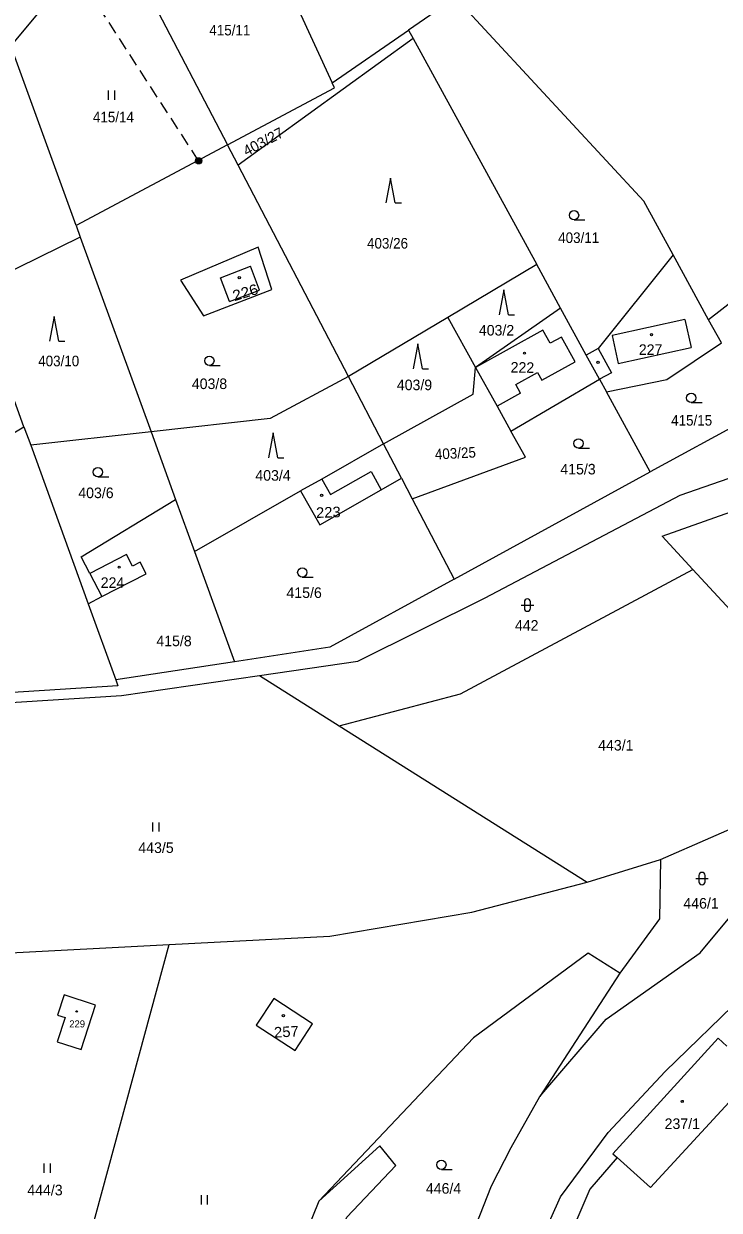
# Model space of a CAD drawing. Extents: x -754445 to -751443, y -1030748 to -1028224.
# Drawn here: x -753502.6 to -753390.6, y -1029073.5 to -1028882.4 of the extents above; entities that cross this region are included whole.
import ezdxf
from ezdxf.enums import TextEntityAlignment as Align

# ---------------------------------------------------------------- set-up
doc = ezdxf.new("R2010")
doc.units = 0
doc.header["$LTSCALE"] = 0.68
doc.linetypes.add('MEDIUM_DASHED', pattern=[4.5, 3, -1.5])
for name, color, linetype, lineweight in [('1', 7, 'Continuous', 25), ('3', 7, 'Continuous', 25), ('4', 7, 'Continuous', 13), ('5', 7, 'Continuous', 25), ('6', 7, 'Continuous', 25)]:
    doc.layers.add(name, color=color, linetype=linetype, lineweight=lineweight)
doc.layers.add('2', color=7, linetype='Continuous')

msp = doc.modelspace()

# ---------------------------------------------------------------- linework, layer by layer
at = {"layer": '1'}
for p, q in [((-753486.58, -1028869.72), (-753469.8, -1028901.88)), ((-753494.17, -1028914.88), (-753504.67, -1028885.95)), ((-753439.88, -1028884.76), (-753468.09, -1028905.15)), ((-753493.5, -1028916.72), (-753510.61, -1028925.11)), ((-753392.33, -1028930.04), (-753398.05, -1028919.59)), ((-753434.31, -1028929.68), (-753450.34, -1028939.19)), ((-753390.28, -1028933.79), (-753392.33, -1028930.04)), ((-753444.68, -1028950.03), (-753450.34, -1028939.19)), ((-753424.16, -1028947.97), (-753409.88, -1028939.64)), ((-753409.88, -1028939.64), (-753408.77, -1028941.67)), ((-753401.72, -1028954.55), (-753408.77, -1028941.67)), ((-753384.17, -1028944.96), (-753401.72, -1028954.55)), ((-753502.57, -1028947.27), (-753501.49, -1028950.26)), ((-753433.31, -1028971.82), (-753401.72, -1028954.55)), ((-753441.79, -1028955.57), (-753440.07, -1028958.87)), ((-753440.07, -1028958.87), (-753433.31, -1028971.82)), ((-753475.12, -1028967.37), (-753468.68, -1028985.12)), ((-753491.97, -1028970.91), (-753490.04, -1028974.64)), ((-753492.25, -1028975.78), (-753490.04, -1028974.64)), ((-753492.25, -1028975.78), (-753487.8, -1028988.05)), ((-753464.67, -1028987.34), (-753451.83, -1028995.43)), ((-753451.83, -1028995.43), (-753411.87, -1029020.64)), ((-753411.87, -1029020.64), (-753400.1, -1029017)), ((-753502.27, -1029115.77), (-753479.19, -1029030.67))]:
    msp.add_line(p, q, dxfattribs=at)
for points in [[(-753445.06, -1028852.06), (-753467.15, -1028860.99), (-753452.93, -1028891.89), (-753440.64, -1028883.38)], [(-753486.58, -1028869.72), (-753493.77, -1028872.77), (-753504.67, -1028885.95)], [(-753398.05, -1028919.59), (-753402.77, -1028910.96), (-753433.06, -1028878.13), (-753440.64, -1028883.38)], [(-753440.64, -1028883.38), (-753439.88, -1028884.76), (-753419.98, -1028921.17)], [(-753469.8, -1028901.88), (-753452.57, -1028892.68), (-753452.93, -1028891.89)], [(-753469.8, -1028901.88), (-753494.17, -1028914.88), (-753493.5, -1028916.72), (-753482.11, -1028948.11)], [(-753450.34, -1028939.19), (-753468.09, -1028905.15), (-753469.8, -1028901.88)], [(-753360.18, -1028918.92), (-753365.3, -1028909.56), (-753367.52, -1028910.77), (-753392.33, -1028930.04)], [(-753398.05, -1028919.59), (-753410.11, -1028934.69), (-753412.02, -1028935.74)], [(-753416.16, -1028928.16), (-753419.98, -1028921.17), (-753434.31, -1028929.68), (-753429.85, -1028937.73)], [(-753516.36, -1028955.52), (-753502.57, -1028947.27), (-753510.61, -1028925.11)], [(-753409.88, -1028939.64), (-753412.02, -1028935.74), (-753416.16, -1028928.16), (-753429.85, -1028937.73)], [(-753408.77, -1028941.67), (-753399.03, -1028939.66), (-753390.28, -1028933.79)], [(-753444.68, -1028950.03), (-753430.23, -1028942.05), (-753429.85, -1028937.73)], [(-753429.85, -1028937.73), (-753426.39, -1028943.95), (-753424.16, -1028947.97)], [(-753450.34, -1028939.19), (-753462.93, -1028945.98), (-753482.11, -1028948.11), (-753501.49, -1028950.26), (-753492.25, -1028975.78)], [(-753482.11, -1028948.11), (-753478.15, -1028959.02), (-753475.12, -1028967.37), (-753458.03, -1028957.63)], [(-753440.07, -1028958.87), (-753421.81, -1028952.2), (-753424.16, -1028947.97)], [(-753444.68, -1028950.03), (-753454.63, -1028955.7), (-753458.03, -1028957.63)], [(-753458.03, -1028957.63), (-753454.93, -1028963.06), (-753445.03, -1028957.42), (-753441.79, -1028955.57), (-753444.68, -1028950.03)], [(-753464.67, -1028987.34), (-753448.8, -1028985.04), (-753428.33, -1028974.85), (-753396.89, -1028958.28), (-753380.08, -1028952.45)], [(-753491.97, -1028970.91), (-753493.35, -1028968.24), (-753478.15, -1028959.02)], [(-753394.88, -1028970.27), (-753399.83, -1028964.93), (-753384.52, -1028959.47), (-753383.05, -1028959.19)], [(-753490.04, -1028974.64), (-753482.9, -1028970.95), (-753483.86, -1028969.08), (-753485.11, -1028969.73), (-753486.07, -1028967.86), (-753491.97, -1028970.91)], [(-753451.83, -1028995.43), (-753432.29, -1028990.28), (-753394.88, -1028970.27)], [(-753400.1, -1029017), (-753375.78, -1029006.35), (-753368.71, -1028998.51), (-753394.88, -1028970.27)], [(-753433.31, -1028971.82), (-753453.33, -1028982.77), (-753468.68, -1028985.12), (-753487.8, -1028988.05)], [(-753542.87, -1028994.11), (-753486.89, -1028990.56), (-753464.67, -1028987.34)], [(-753487.8, -1028988.05), (-753487.46, -1028988.99), (-753543.25, -1028992.53)], [(-753419.48, -1029055.17), (-753408.84, -1029042.69), (-753393.71, -1029032.01), (-753367.2, -1029000.13)], [(-753429.75, -1029105.16), (-753421.74, -1029083.85), (-753416.16, -1029071.29), (-753408.48, -1029060.98), (-753399.35, -1029051.11), (-753386.69, -1029038.91), (-753366.27, -1029014.04), (-753360.62, -1029006.78)], [(-753400.1, -1029017), (-753400.26, -1029026.56), (-753406.62, -1029035.28), (-753419.48, -1029055.17)], [(-753479.19, -1029030.67), (-753453.33, -1029029.34), (-753430.47, -1029025.45), (-753411.87, -1029020.64)], [(-753509.96, -1029032.69), (-753506.86, -1029032.1), (-753479.19, -1029030.67)], [(-753406.62, -1029035.28), (-753411.75, -1029032.05), (-753430.17, -1029045.73), (-753455.08, -1029072.04)], [(-753389.38, -1029047.03), (-753390.8, -1029045.77), (-753407.74, -1029064.38), (-753407.08, -1029064.97)], [(-753387.07, -1029049.07), (-753384.63, -1029051.28), (-753401.69, -1029069.8), (-753407.08, -1029064.97)], [(-753432.81, -1029083.61), (-753427.28, -1029069.54), (-753424.11, -1029063.37), (-753419.48, -1029055.17)], [(-753451.45, -1029076.65), (-753450.56, -1029074.58), (-753442.7, -1029066.25), (-753445.26, -1029063.11), (-753455.08, -1029072.04)], [(-753407.08, -1029064.97), (-753411.46, -1029070.06), (-753424.42, -1029100.44), (-753425.02, -1029110.67)], [(-753455.08, -1029072.04), (-753467.29, -1029102.21), (-753462.39, -1029104.53)]]:
    msp.add_lwpolyline(points, dxfattribs=at)
for points in [[(-753462.66, -1028925.16), (-753464.86, -1028918.37), (-753477.35, -1028923.65), (-753473.69, -1028929.42)], [(-753493.37, -1029047.6), (-753491.06, -1029040.46), (-753496.09, -1029038.8), (-753497.16, -1029042.03), (-753495.92, -1029042.44), (-753497.22, -1029046.37)], [(-753462.33, -1029039.36), (-753465.16, -1029043.66), (-753458.93, -1029047.75), (-753456.1, -1029043.44)]]:
    msp.add_lwpolyline(points, close=True, dxfattribs=at)
at = {"layer": '3'}
for p, q in [((-753488.951, -1028894.62), (-753488.951, -1028893.12)), ((-753487.95, -1028894.62), (-753487.95, -1028893.12)), ((-753442.8, -1028911.22), (-753441.804, -1028911.22)), ((-753414.003, -1028913.97), (-753412.253, -1028913.97)), ((-753424.57, -1028929.23), (-753423.574, -1028929.23)), ((-753496.97, -1028933.5), (-753495.974, -1028933.5)), ((-753472.723, -1028937.4), (-753470.973, -1028937.4)), ((-753438.41, -1028937.94), (-753437.414, -1028937.94)), ((-753395.133, -1028943.39), (-753393.383, -1028943.39)), ((-753413.283, -1028950.72), (-753411.533, -1028950.72)), ((-753461.71, -1028952.27), (-753460.714, -1028952.27)), ((-753490.673, -1028955.35), (-753488.923, -1028955.35)), ((-753457.753, -1028971.5), (-753456.003, -1028971.5)), ((-753422.501, -1028976.001), (-753420.499, -1028976.001)), ((-753422.001, -1028975.501), (-753422.001, -1028976.502)), ((-753420.999, -1028976.502), (-753420.999, -1028975.501)), ((-753481.821, -1029012.5), (-753481.821, -1029011)), ((-753480.82, -1029012.5), (-753480.82, -1029011)), ((-753394.381, -1029020.061), (-753392.379, -1029020.061)), ((-753393.881, -1029019.561), (-753393.881, -1029020.562)), ((-753392.879, -1029020.562), (-753392.879, -1029019.561)), ((-753499.301, -1029067.45), (-753499.301, -1029065.95)), ((-753498.3, -1029067.45), (-753498.3, -1029065.95)), ((-753435.363, -1029066.9), (-753433.613, -1029066.9)), ((-753474.011, -1029072.53), (-753474.011, -1029071.03)), ((-753473.01, -1029072.53), (-753473.01, -1029071.03))]:
    msp.add_line(p, q, dxfattribs=at)
for points in [[(-753442.8, -1028911.22), (-753443.55, -1028907.22), (-753444.3, -1028911.22)], [(-753424.57, -1028929.23), (-753425.32, -1028925.23), (-753426.07, -1028929.23)], [(-753496.97, -1028933.5), (-753497.72, -1028929.5), (-753498.47, -1028933.5)], [(-753438.41, -1028937.94), (-753439.16, -1028933.94), (-753439.91, -1028937.94)], [(-753461.71, -1028952.27), (-753462.46, -1028948.27), (-753463.21, -1028952.27)]]:
    msp.add_lwpolyline(points, dxfattribs=at)
for centre in [(-753414.0029, -1028913.2198), (-753472.7229, -1028936.6498), (-753395.1329, -1028942.6398), (-753413.2829, -1028949.9698), (-753490.6729, -1028954.5998), (-753457.7529, -1028970.7498), (-753435.3629, -1029066.1498)]:
    msp.add_circle(centre, 0.75, dxfattribs=at)
for centre, start, end in [((-753421.5, -1028975.5009), 0, 180), ((-753421.5, -1028976.5009), 180, 359.98789), ((-753393.38, -1029019.5609), 0, 180), ((-753393.38, -1029020.5609), 180, 359.98789)]:
    msp.add_arc(centre, 0.5, start, end, dxfattribs=at)
at = {"layer": '4'}
for p, q in [((-753470.93, -1028923.27), (-753466.07, -1028921.43)), ((-753464.62, -1028925.27), (-753466.07, -1028921.43)), ((-753469.48, -1028927.1), (-753470.93, -1028923.27)), ((-753469.48, -1028927.1), (-753464.62, -1028925.27)), ((-753396.14, -1028929.99), (-753407.87, -1028932.56)), ((-753396.14, -1028929.99), (-753395.15, -1028934.53)), ((-753419, -1028931.71), (-753429.85, -1028937.73)), ((-753417.82, -1028933.84), (-753419, -1028931.71)), ((-753416.04, -1028932.85), (-753417.82, -1028933.84)), ((-753413.83, -1028936.83), (-753416.04, -1028932.85)), ((-753407.87, -1028932.56), (-753406.87, -1028937.1)), ((-753410.11, -1028934.69), (-753407.98, -1028938.6)), ((-753406.87, -1028937.1), (-753395.15, -1028934.53)), ((-753419.19, -1028939.8), (-753413.83, -1028936.83)), ((-753423.39, -1028940.48), (-753419.89, -1028938.54)), ((-753419.89, -1028938.54), (-753419.19, -1028939.8)), ((-753407.98, -1028938.6), (-753409.88, -1028939.64)), ((-753422.62, -1028941.86), (-753426.39, -1028943.95)), ((-753422.62, -1028941.86), (-753423.39, -1028940.48)), ((-753453.19, -1028958.22), (-753446.69, -1028954.51)), ((-753446.69, -1028954.51), (-753445.03, -1028957.42)), ((-753454.63, -1028955.7), (-753453.19, -1028958.22))]:
    msp.add_line(p, q, dxfattribs=at)
at = {"layer": '5'}
for centre, radius in [((-753467.9067, -1028923.2586), 0.175), ((-753401.5168, -1028932.4492), 0.175), ((-753421.9668, -1028935.4392), 0.175), ((-753410.1268, -1028936.9192), 0.175), ((-753454.6368, -1028958.3392), 0.175), ((-753487.2468, -1028969.8892), 0.175), ((-753494.0846, -1029041.4494), 0.1172), ((-753460.8068, -1029042.1292), 0.175), ((-753396.5768, -1029055.9492), 0.175)]:
    msp.add_circle(centre, radius, dxfattribs=at)
at = {"layer": '6', "linetype": 'MEDIUM_DASHED'}
msp.add_line((-753474.45, -1028904.45), (-753499.83, -1028865.29), dxfattribs=at)
at = {"layer": '6'}
for radius in [0.5, 0.4, 0.3, 0.2, 0.1]:
    msp.add_circle((-753474.4534, -1028904.4499), radius, dxfattribs=at)

# ---------------------------------------------------------------- texts
at = {"layer": '2', "width": 0.95}
for s, p in [('415/11', (-753469.419, -1028884.25)), ('415/14', (-753488.169, -1028898.25)), ('403/26', (-753444.029, -1028918.58)), ('403/11', (-753413.249, -1028917.68)), ('403/10', (-753496.979, -1028937.54)), ('415/15', (-753395.059, -1028947.1))]:
    msp.add_text(s, height=1.7, dxfattribs=at).set_placement(p, align=Align.CENTER)
at = {"layer": '2'}
for s, rotation, p in [('403/27', 28, (-753463.6441, -1028902.1085)), ('222', 359, (-753422.3248, -1028938.5796))]:
    msp.add_text(s, height=1.7, rotation=rotation, dxfattribs=at).set_placement(p, align=Align.CENTER)
for s, rotation, width, p in [('226', 17, 1.1, (-753466.686, -1028926.452)), ('403/25', 3, 0.95, (-753433.065, -1028952.3964)), ('223', 2, 1.05, (-753453.5297, -1028961.9084)), ('257', 3, 1.05, (-753460.275, -1029045.5771))]:
    msp.add_text(s, height=1.7, rotation=rotation, dxfattribs=dict(at, width=width)).set_placement(p, align=Align.CENTER)
for s, height, p in [('403/2', 1.7, (-753426.48, -1028932.59)), ('227', 1.7, (-753401.669, -1028935.71)), ('403/8', 1.7, (-753472.7, -1028941.21)), ('403/9', 1.7, (-753439.69, -1028941.39)), ('415/3', 1.7, (-753413.36, -1028954.96)), ('403/4', 1.7, (-753462.47, -1028955.97)), ('403/6', 1.7, (-753490.98, -1028958.78)), ('224', 1.7, (-753488.319, -1028973.24)), ('415/6', 1.7, (-753457.46, -1028974.86)), ('442', 1.7, (-753421.619, -1028980.13)), ('415/8', 1.7, (-753478.41, -1028982.63)), ('443/1', 1.7, (-753407.27, -1028999.43)), ('443/5', 1.7, (-753481.31, -1029015.93)), ('446/1', 1.7, (-753393.55, -1029024.89)), ('229', 1.14, (-753494.01, -1029044.03)), ('237/1', 1.7, (-753396.57, -1029060.39)), ('444/3', 1.7, (-753499.19, -1029071.08)), ('446/4', 1.7, (-753435.01, -1029070.81))]:
    msp.add_text(s, height=height, dxfattribs=at).set_placement(p, align=Align.CENTER)

doc.saveas('drawing.dxf')
